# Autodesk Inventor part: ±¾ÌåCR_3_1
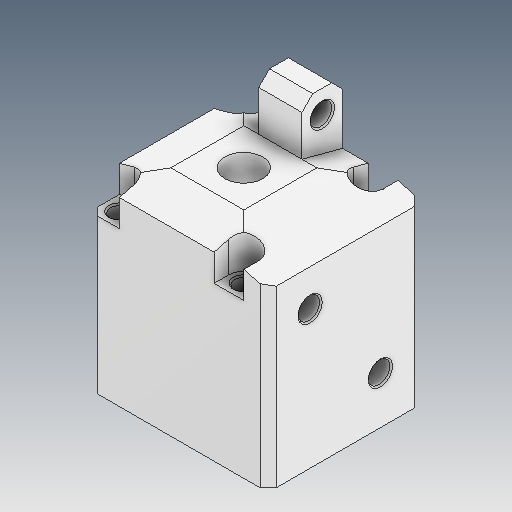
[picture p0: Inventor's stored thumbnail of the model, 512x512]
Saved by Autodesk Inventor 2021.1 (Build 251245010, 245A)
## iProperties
Created: 2021-05
Part Number: ±¾ÌåCR_3_1
Material: Ogólny
Document SubType Name: Modeling
Designer: user
Density: 1 g/cm^3
Appearance: Domyślna
Author: user
Revision Number: ÈÎºÎ
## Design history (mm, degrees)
feature "ÊäÈë1"
node "Bryła1"
